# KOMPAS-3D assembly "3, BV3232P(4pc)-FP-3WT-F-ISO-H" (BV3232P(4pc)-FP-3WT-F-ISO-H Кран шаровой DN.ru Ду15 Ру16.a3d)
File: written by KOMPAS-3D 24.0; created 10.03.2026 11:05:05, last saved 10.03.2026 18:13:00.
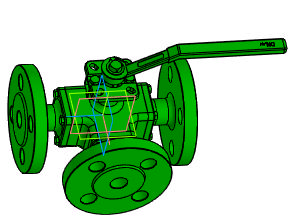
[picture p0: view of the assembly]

Document properties: Автор: R2D2; Полное имя файла: E:\Работа\Зайцев\BV3232P(4pc)-FP-3WT-F-ISO-H Кран шаровой DN.ru Ду15-100 Ру16\DN15\исходные материалы\BV3232P(4pc)-FP-3WT-F-ISO-H Кран шаровой DN.ru Ду15 Ру16.a3d

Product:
- Component [assembly]: Сборка1  | qty 1  | pos. 1  | Масса: 3.494716; Автор: R2D2; source file: dn15_3d_step.a3d
- Part/product: 3  | designation BV3232P(4pc)-FP-3WT-F-ISO-H
    Масса: 3.5
    Раздел спецификации: Прочие изделия
    Примечание: D160-36346

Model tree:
1. Эскиз:1  (labels: Грань.Твердое тело1; Ребро.Твердое тело1)
2. Элемент выдавливания:1  (labels: Грань.Твердое тело1; Твердое тело1)
     Расстояние 2 = 0.01

Referenced files in E:\Работа\Зайцев\BV3232P(4pc)-FP-3WT-F-ISO-H Кран шаровой DN.ru Ду15-100 Ру16\DN15\исходные материалы\: dn15_3d_step.a3d
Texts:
  BV3232P(4pc)-FP-3WT-F-ISO-H
  Сборка1 Сборка1
  Ось Z.Начало координат
  Ось Y.Начало координат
